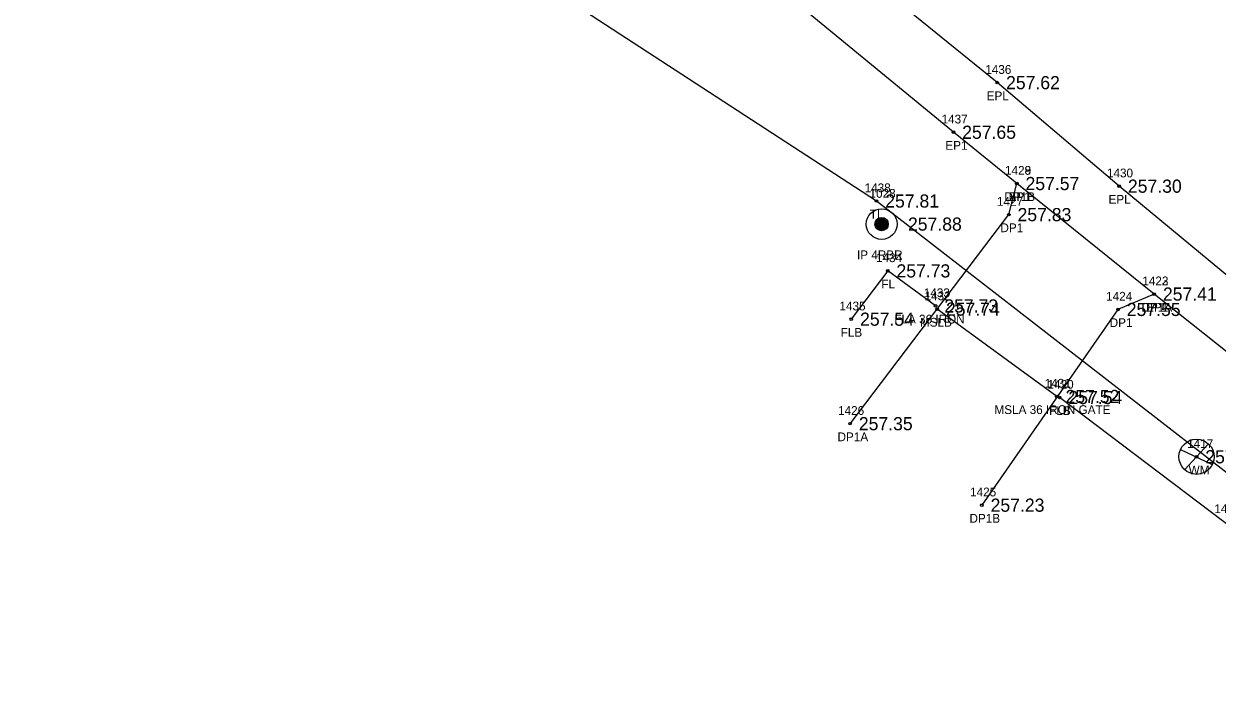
# Model space of a CAD drawing. Extents: x 1961231 to 1962574, y 799865 to 801120.
# Drawn here: x 1961812.2 to 1961948.3, y 800515.1 to 800591.6 of the extents above; entities that cross this region are included whole.
import ezdxf

# ---------------------------------------------------------------- set-up
doc = ezdxf.new("R2010")
doc.units = 0
for name, color, linetype in [('RD_EX_Driveway', 7, 'Continuous'), ('RD_EX_Driveway_txCode', 7, 'Continuous'), ('RD_EX_DV_Prop_txCode', 7, 'Continuous'), ('RD_EX_DV_PropPin', 7, 'Continuous'), ('RD_EX_Fence_Other', 7, 'Continuous'), ('RD_EX_Fence_Other_txCode', 7, 'Continuous'), ('RD_EX_Misc', 7, 'Continuous'), ('RD_EX_Misc_txCode', 7, 'Continuous'), ('RD_EX_Road', 7, 'Continuous'), ('RD_EX_Road_txCode', 7, 'Continuous'), ('RD_EX_TX_Driveway_ELEV', 7, 'Continuous'), ('RD_EX_TX_DV_Prop_ELEV', 7, 'Continuous'), ('RD_EX_TX_Fence_Other_ELEV', 7, 'Continuous'), ('RD_EX_TX_Misc_ELEV', 7, 'Continuous'), ('RD_EX_TX_Road_ELEV', 7, 'Continuous'), ('RD_EX_TX_UT_ELEV', 7, 'Continuous'), ('RD_EX_TX_VEG_ELEV', 7, 'Continuous'), ('RD_EX_UT', 7, 'Continuous'), ('RD_EX_UT_txCode', 7, 'Continuous'), ('RD_EX_VEG', 7, 'Continuous'), ('RD_EX_VEG_txCode', 7, 'Continuous'), ('RD_SMD_Locator', 7, 'Continuous')]:
    doc.layers.add(name, color=color, linetype=linetype)

msp = doc.modelspace()

# ---------------------------------------------------------------- linework, layer by layer
at = {"layer": 'RD_EX_Driveway'}
for points in [[(1961906.41, 800546.06), (1961924.5, 800569.87), (1961925.41, 800573.41)], [(1961941.07, 800560.82), (1961936.95, 800559.07), (1961921.43, 800536.78)]]:
    msp.add_lwpolyline(points, dxfattribs=at)
at = {"layer": 'RD_EX_DV_PropPin'}
for p, q in [((1961909.28, 800568.6), (1961909.28, 800568.99)), ((1961909.31, 800568.49), (1961909.31, 800569.09)), ((1961909.35, 800568.42), (1961909.35, 800569.16)), ((1961909.38, 800568.37), (1961909.38, 800569.22)), ((1961909.42, 800568.32), (1961909.42, 800569.27)), ((1961909.45, 800568.28), (1961909.45, 800569.31)), ((1961909.49, 800568.24), (1961909.49, 800569.34)), ((1961909.52, 800568.21), (1961909.52, 800569.37)), ((1961909.56, 800568.18), (1961909.56, 800569.4)), ((1961909.59, 800568.16), (1961909.59, 800569.43)), ((1961909.63, 800568.14), (1961909.63, 800569.45)), ((1961909.66, 800568.12), (1961909.66, 800569.47)), ((1961909.7, 800568.1), (1961909.7, 800569.48)), ((1961909.73, 800568.08), (1961909.73, 800569.5)), ((1961909.77, 800568.07), (1961909.77, 800569.51)), ((1961909.8, 800568.06), (1961909.8, 800569.52)), ((1961909.84, 800568.05), (1961909.84, 800569.53)), ((1961909.87, 800568.04), (1961909.87, 800569.54)), ((1961909.91, 800568.04), (1961909.91, 800569.55)), ((1961909.94, 800568.03), (1961909.94, 800569.55)), ((1961909.98, 800568.03), (1961909.98, 800569.55)), ((1961910.01, 800568.03), (1961910.01, 800569.55)), ((1961910.05, 800568.03), (1961910.05, 800569.55)), ((1961910.08, 800568.03), (1961910.08, 800569.55)), ((1961910.12, 800568.04), (1961910.12, 800569.55)), ((1961910.15, 800568.04), (1961910.15, 800569.54)), ((1961910.19, 800568.05), (1961910.19, 800569.53)), ((1961910.22, 800568.06), (1961910.22, 800569.52)), ((1961910.26, 800568.07), (1961910.26, 800569.51)), ((1961910.29, 800568.08), (1961910.29, 800569.5)), ((1961910.33, 800568.1), (1961910.33, 800569.48)), ((1961910.36, 800568.12), (1961910.36, 800569.47)), ((1961910.4, 800568.14), (1961910.4, 800569.45)), ((1961910.43, 800568.16), (1961910.43, 800569.43)), ((1961910.47, 800568.18), (1961910.47, 800569.4)), ((1961910.5, 800568.21), (1961910.5, 800569.37)), ((1961910.54, 800568.24), (1961910.54, 800569.34)), ((1961910.57, 800568.28), (1961910.57, 800569.31)), ((1961910.61, 800568.32), (1961910.61, 800569.27)), ((1961910.64, 800568.37), (1961910.64, 800569.22)), ((1961910.68, 800568.42), (1961910.68, 800569.16)), ((1961910.71, 800568.49), (1961910.71, 800569.09)), ((1961910.75, 800568.6), (1961910.75, 800568.99))]:
    msp.add_line(p, q, dxfattribs=at)
for radius in [1.75, 0.761]:
    msp.add_circle((1961910.01, 800568.79), radius, dxfattribs=at)
at = {"layer": 'RD_EX_Fence_Other'}
for points in [[(1961916.15, 800559.47), (1961910.7, 800563.46), (1961906.55, 800557.96)], [(1961958.32, 800527.94), (1961949.02, 800534.87), (1961930.3, 800549.04)]]:
    msp.add_lwpolyline(points, dxfattribs=at)
at = {"layer": 'RD_EX_Misc'}
msp.add_line((1961929.97, 800549.16), (1961916.34, 800559.11), dxfattribs=at)
at = {"layer": 'RD_EX_Road'}
for points in [[(1962241.79, 800315.68), (1962238.35, 800317.6), (1962189.92, 800352.69), (1962151.64, 800383.49), (1962113.78, 800416.39), (1962074.11, 800451.29), (1962034.78, 800486.96), (1962017.07, 800503.17), (1961999.46, 800519.25), (1961962.48, 800552.12), (1961937.08, 800573.11), (1961923.19, 800584.9), (1961883.07, 800617.43), (1961838.29, 800653.43), (1961801.42, 800682.57), (1961728.41, 800740.86), (1961722.95, 800745.11), (1961689.13, 800771.93)], [(1961992.53, 800418.34), (1962000.94, 800437), (1962011.01, 800464.81), (1962016.84, 800481.64), (1962015.31, 800499.65), (1961996.99, 800516.71), (1961979.47, 800530.76), (1961969.8, 800538.75), (1961958.28, 800547.16), (1961941.07, 800560.82), (1961925.41, 800573.41), (1961918.19, 800579.25), (1961879.32, 800611.18), (1961866.07, 800621.08), (1961838.29, 800653.43)]]:
    msp.add_lwpolyline(points, dxfattribs=at)
at = {"layer": 'RD_EX_UT'}
for p, q in [((1961944.07, 800543.13), (1961947.7, 800541.41)), ((1961944.55, 800540.83), (1961947.22, 800543.73))]:
    msp.add_line(p, q, dxfattribs=at)
msp.add_circle((1961945.9, 800542.29), 2, dxfattribs=at)
at = {"layer": 'RD_EX_VEG'}
msp.add_lwpolyline([(1961986.16, 800417.05), (1962008.73, 800486.69), (1961986.14, 800509.28), (1961949.4, 800540.42), (1961909.42, 800571.42), (1961867.44, 800598.73), (1961825.04, 800634.78), (1961788.24, 800662.23), (1961745.49, 800697.38)], dxfattribs=at)
at = {"layer": 'RD_SMD_Locator'}
for centre in [(1961923.19, 800584.9), (1961918.19, 800579.25), (1961925.41, 800573.41), (1961925.41, 800573.41), (1961937.08, 800573.11), (1961909.42, 800571.42), (1961910.01, 800568.79), (1961924.5, 800569.87), (1961910.7, 800563.46), (1961941.07, 800560.82), (1961941.07, 800560.82), (1961916.15, 800559.47), (1961906.55, 800557.96), (1961916.34, 800559.11), (1961936.95, 800559.07), (1961929.97, 800549.16), (1961930.3, 800549.04), (1961906.41, 800546.06), (1961945.9, 800542.29), (1961921.43, 800536.78)]:
    msp.add_circle(centre, 0.15, dxfattribs=at)

# ---------------------------------------------------------------- texts
at = {"layer": 'RD_EX_Driveway_txCode'}
for s, p in [('1428', (1961924.07, 800574.41)), ('1427', (1961923.15, 800570.87)), ('DP1B', (1961924, 800571.41)), ('DP1', (1961923.55, 800567.87)), ('1423', (1961939.72, 800561.82)), ('1424', (1961935.6, 800560.07)), ('DP1A', (1961939.63, 800558.82)), ('DP1', (1961936, 800557.07)), ('1426', (1961905.04, 800547.06)), ('DP1A', (1961904.98, 800544.06)), ('1425', (1961920.09, 800537.78)), ('DP1B', (1961920.02, 800534.78))]:
    msp.add_text(s, height=1, dxfattribs=at).set_placement(p)
at = {"layer": 'RD_EX_DV_Prop_txCode'}
for s, p in [('1028', (1961908.63, 800571.79)), ('IP 4RBR', (1961907.2, 800564.79))]:
    msp.add_text(s, height=1, dxfattribs=at).set_placement(p)
at = {"layer": 'RD_EX_Fence_Other_txCode'}
for s, p in [('1434', (1961909.36, 800564.46)), ('FL', (1961909.97, 800561.46)), ('1433', (1961914.81, 800560.47)), ('1435', (1961905.2, 800558.96)), ('FLA 36 IRON', (1961911.45, 800557.47)), ('FLB', (1961905.34, 800555.96)), ('1420', (1961928.92, 800550.04)), ('FLB', (1961929.1, 800547.04)), ('1416', (1961947.93, 800535.87))]:
    msp.add_text(s, height=1, dxfattribs=at).set_placement(p)
at = {"layer": 'RD_EX_Misc_txCode'}
for s, p in [('1432', (1961914.9, 800560.11)), ('MSLB', (1961914.37, 800557.11)), ('1431', (1961928.59, 800550.16)), ('MSLA 36 IRON GATE', (1961922.87, 800547.16))]:
    msp.add_text(s, height=1, dxfattribs=at).set_placement(p)
at = {"layer": 'RD_EX_Road_txCode'}
for s, p in [('1436', (1961921.82, 800585.9)), ('EPL', (1961921.98, 800582.9)), ('1437', (1961916.84, 800580.25)), ('EP1', (1961917.27, 800577.25)), ('1429', (1961924.07, 800574.41)), ('1430', (1961935.69, 800574.11)), ('EP1', (1961924.49, 800571.41)), ('EPL', (1961935.87, 800571.11)), ('1422', (1961939.72, 800561.82)), ('EP1', (1961940.15, 800558.82))]:
    msp.add_text(s, height=1, dxfattribs=at).set_placement(p)
at = {"layer": 'RD_EX_TX_Driveway_ELEV'}
for s, p in [('257.57', (1961926.41, 800572.66)), ('257.83', (1961925.5, 800569.12)), ('257.41', (1961942.07, 800560.07)), ('257.55', (1961937.95, 800558.32)), ('257.35', (1961907.41, 800545.31)), ('257.23', (1961922.43, 800536.03))]:
    msp.add_text(s, height=1.5, dxfattribs=at).set_placement(p)
at = {"layer": 'RD_EX_TX_DV_Prop_ELEV'}
msp.add_text('257.88', height=1.5, dxfattribs=at).set_placement((1961913.01, 800568.04))
at = {"layer": 'RD_EX_TX_Fence_Other_ELEV'}
for s, p in [('257.73', (1961911.7, 800562.71)), ('257.73', (1961917.15, 800558.72)), ('257.54', (1961907.55, 800557.21)), ('257.54', (1961931.3, 800548.29))]:
    msp.add_text(s, height=1.5, dxfattribs=at).set_placement(p)
at = {"layer": 'RD_EX_TX_Misc_ELEV'}
for s, p in [('257.74', (1961917.34, 800558.36)), ('257.52', (1961930.97, 800548.41))]:
    msp.add_text(s, height=1.5, dxfattribs=at).set_placement(p)
at = {"layer": 'RD_EX_TX_Road_ELEV'}
for s, p in [('257.62', (1961924.19, 800584.15)), ('257.65', (1961919.19, 800578.5)), ('257.57', (1961926.41, 800572.66)), ('257.30', (1961938.08, 800572.36)), ('257.41', (1961942.07, 800560.07))]:
    msp.add_text(s, height=1.5, dxfattribs=at).set_placement(p)
at = {"layer": 'RD_EX_TX_UT_ELEV'}
msp.add_text('257.16', height=1.5, dxfattribs=at).set_placement((1961946.9, 800541.54))
at = {"layer": 'RD_EX_TX_VEG_ELEV'}
msp.add_text('257.81', height=1.5, dxfattribs=at).set_placement((1961910.42, 800570.67))
at = {"layer": 'RD_EX_UT_txCode'}
for s, p in [('1417', (1961944.84, 800543.29)), ('WM', (1961945, 800540.29))]:
    msp.add_text(s, height=1, dxfattribs=at).set_placement(p)
at = {"layer": 'RD_EX_VEG_txCode'}
for s, p in [('1438', (1961908.07, 800572.42)), ('TL', (1961908.65, 800569.42))]:
    msp.add_text(s, height=1, dxfattribs=at).set_placement(p)

doc.saveas('drawing.dxf')
